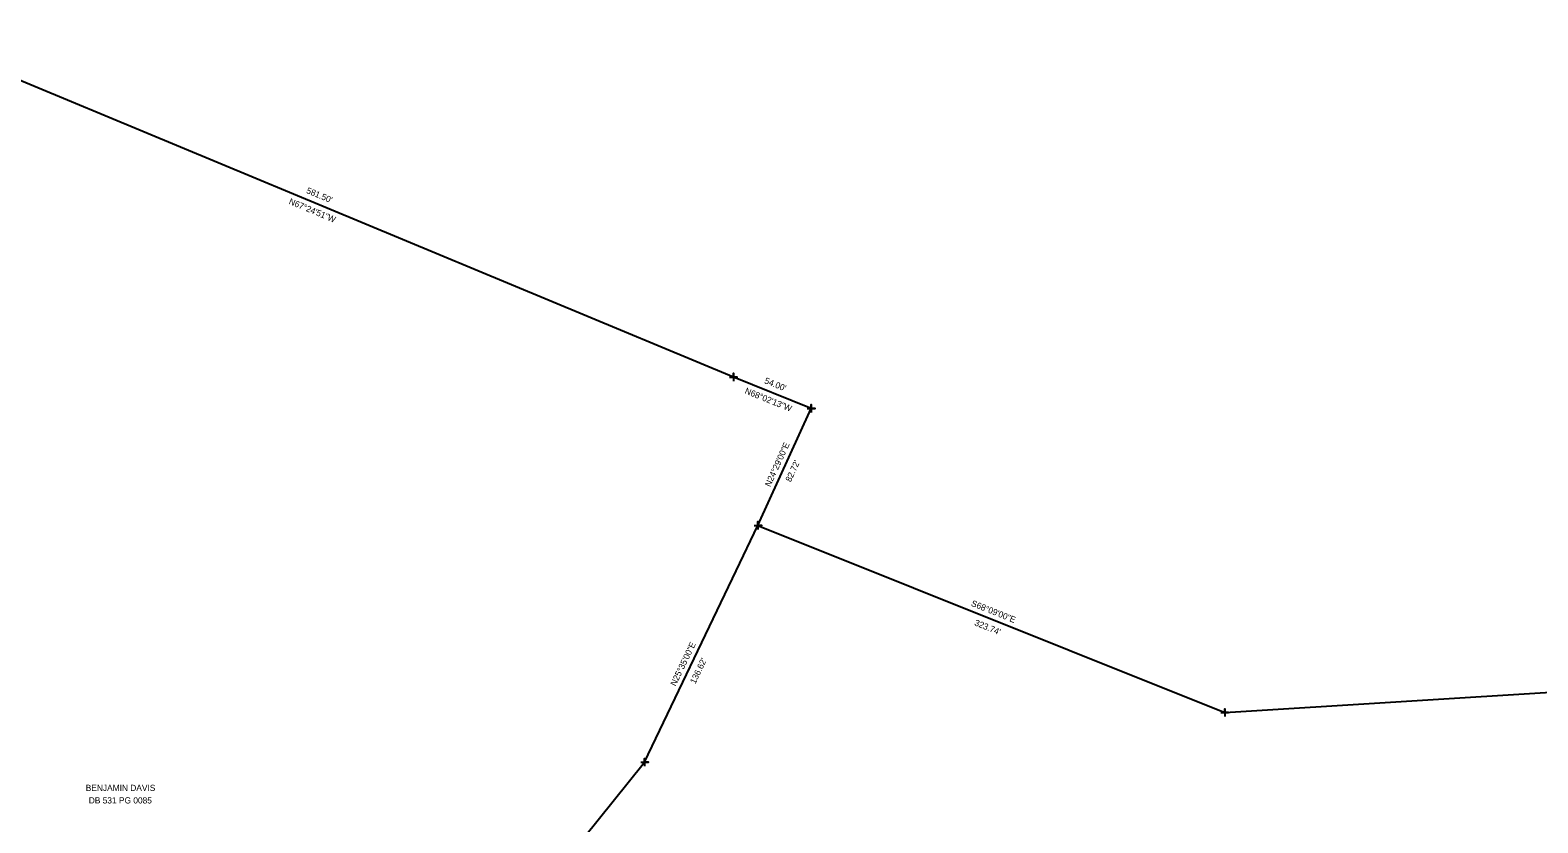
# Model space of a CAD drawing. Extents: x 1121294 to 1124558, y 901107 to 903080.
# Drawn here: x 1122827 to 1123798, y 902098 to 902609 of the extents above; entities that cross this region are included whole.
import ezdxf

# ---------------------------------------------------------------- set-up
doc = ezdxf.new("R2010")
doc.units = 0
for name, color, linetype in [('CTL Secondary Horizontal and Vertical CELL', 7, 'Continuous'), ('CTL Vertical Benchmark CELL', 7, 'Continuous'), ('Exist Survey Observation Group', 7, 'Continuous')]:
    doc.layers.add(name, color=color, linetype=linetype)

msp = doc.modelspace()

# ---------------------------------------------------------------- linework, layer by layer
at = {"layer": 'CTL Secondary Horizontal and Vertical CELL'}
for p, q in [((1123279.92, 902385.35), (1122743.02, 902608.69)), ((1123330, 902365.16), (1123279.92, 902385.35)), ((1123295.72, 902289.87), (1123330, 902365.16)), ((1123295.72, 902289.87), (1123330, 902365.16)), ((1123281.74, 902260.67), (1123295.72, 902289.87)), ((1123295.72, 902289.87), (1123596.21, 902169.38)), ((1123222.74, 902137.44), (1123281.74, 902260.67)), ((1123596.21, 902169.38), (1124555.56, 902230.02)), ((1123114.89, 902003.46), (1123222.74, 902137.44))]:
    msp.add_line(p, q, dxfattribs=at)
at = {"layer": 'CTL Vertical Benchmark CELL'}
for p, q in [((1123279.92, 902385.35), (1123279.92, 902385.35)), ((1123330, 902365.16), (1123330, 902365.16)), ((1123295.72, 902289.87), (1123295.72, 902289.87)), ((1123596.21, 902169.38), (1123596.21, 902169.38)), ((1123222.74, 902137.44), (1123222.74, 902137.44))]:
    msp.add_line(p, q, dxfattribs=at)
for points in [[(1123277.42, 902385.35), (1123282.42, 902385.35), (1123279.92, 902385.35), (1123279.92, 902387.85), (1123279.92, 902382.85)], [(1123327.5, 902365.16), (1123332.5, 902365.16), (1123330, 902365.16), (1123330, 902367.66), (1123330, 902362.66)], [(1123293.22, 902289.87), (1123298.22, 902289.87), (1123295.72, 902289.87), (1123295.72, 902292.37), (1123295.72, 902287.37)], [(1123593.71, 902169.38), (1123598.71, 902169.38), (1123596.21, 902169.38), (1123596.21, 902171.88), (1123596.21, 902166.88)], [(1123220.24, 902137.44), (1123225.24, 902137.44), (1123222.74, 902137.44), (1123222.74, 902139.94), (1123222.74, 902134.94)]]:
    msp.add_lwpolyline(points, dxfattribs=at)

# ---------------------------------------------------------------- texts
at = {"layer": 'Exist Survey Observation Group'}
for s, rotation, p in [('N67°24\'51"W', 337.4143, (1122993.38, 902496.94)), ("581.50'", 337.4143, (1123004.62, 902503.96)), ("54.00'", 338.03708, (1123299.49, 902381.54)), ('N68°02\'13"W', 338.03708, (1123286.88, 902374.98)), ('N24°29\'00"E', 65.51667, (1123303.6, 902314.4)), ("82.72'", 65.51667, (1123316.88, 902317.52)), ('S68°09\'00"E', 338.15, (1123432.58, 902238.23)), ("323.74'", 338.15, (1123434.72, 902225.73)), ('N25°35\'00"E', 64.41667, (1123242.72, 902186.12)), ("136.62'", 64.41667, (1123255.4, 902187.58))]:
    msp.add_text(s, height=4.02, rotation=rotation, dxfattribs=at).set_placement(p)
for s, p in [('BENJAMIN DAVIS', (1122863.04, 902118.96)), ('DB 531 PG 0085', (1122864.98, 902110.92))]:
    msp.add_text(s, height=4.02, dxfattribs=at).set_placement(p)

doc.saveas('drawing.dxf')
